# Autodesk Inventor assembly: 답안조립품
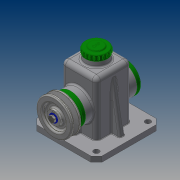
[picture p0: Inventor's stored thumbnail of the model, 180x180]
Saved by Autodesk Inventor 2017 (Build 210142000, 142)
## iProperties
Part Number: 답안조립품
Material: 일반
Document SubType Name: Assembly
Designer: 20
Author: 20
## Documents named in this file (14)
- C:\Users\20\Desktop\470818V1017\답안조립품.iam
- C:\Users\20\Desktop\470818V1017\본체.ipt
- C:\Users\20\Desktop\470818V1017\뒤커버.ipt
- C:\Users\20\Desktop\470818V1017\앞커버.ipt
- C:\Users\20\Desktop\470818V1017\베어링 15 x 35 x 11.ipt
- C:\Users\20\Desktop\470818V1017\멈춤링 15 x 1.ipt
- C:\Users\20\Desktop\470818V1017\축.ipt
- C:\Users\20\Desktop\470818V1017\오일실 15 25 7.ipt
- C:\Users\20\Desktop\470818V1017\상부캡.ipt
- C:\Users\20\Desktop\470818V1017\V-벨트풀리.ipt
- C:\Users\20\Desktop\470818V1017\키 5 x 5 x 14.ipt
- C:\Users\20\Desktop\470818V1017\와셔.ipt
- C:\Users\20\Desktop\470818V1017\볼트 M6 x 12.ipt
- C:\Users\20\Desktop\470818V1017\볼트 M4 x 10.ipt
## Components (1 placed, 1 different names)
1. V-벨트풀리:1 — 플러쉬:1, 플러쉬:2
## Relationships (2: Flush 2)
- 플러쉬:1 [Flush]: V-벨트풀리:1
- 플러쉬:2 [Flush]: V-벨트풀리:1
